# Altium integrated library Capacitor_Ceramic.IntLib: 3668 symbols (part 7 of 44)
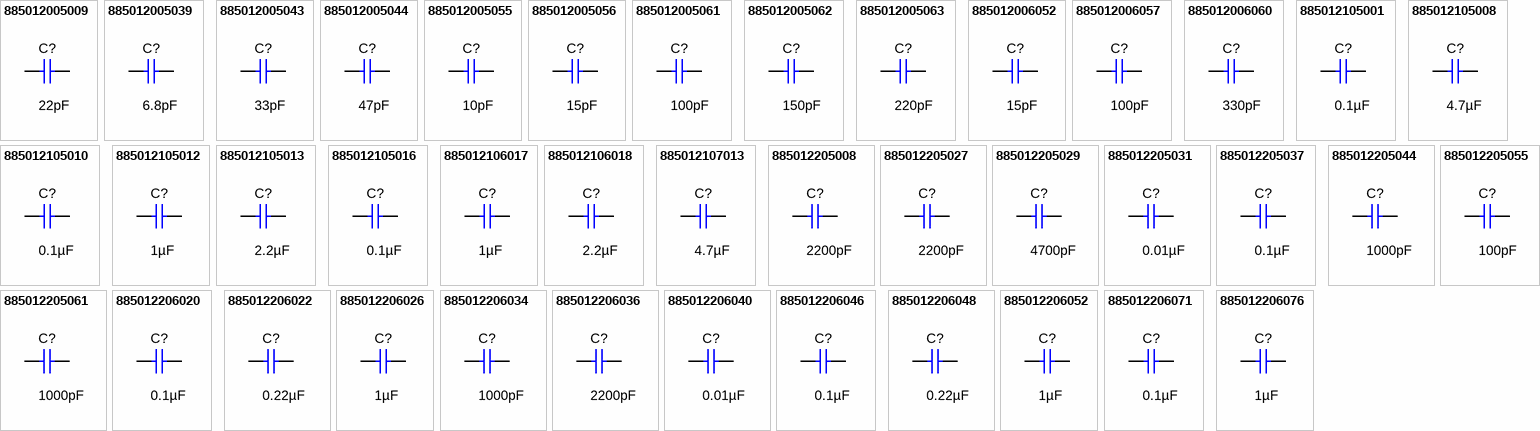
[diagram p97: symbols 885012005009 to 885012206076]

## 885012206076
designator C?  ValueDisplayed: 1µF  (hidden comment: 885012206076)
CAP, CERM, 1 µF, 25 V,+/- 10%, X7R, 0603; Manufacturer: Wurth Elektronik; Polarized: N; CompType: Capacitor; Value: 1uF; U/M: EA; Cap_F: 0.000001; Tolerance_%: 10; VDC_V: 25; Value2: 25V; TaMin_C: -55; TaMax_C: 125; Cap_Case: 0603; SizeArea_mm2: 1.28; SizeAreaWB_mm2: 4.68; SizeX_mm: 1.6; SizeY_mm: 0.8; SizeZ_mm: 1; AEC Category: Q200; Green_Lifecycle: Not Set; Green_REACh: Incomplete
signal-integrity model Cap
simulation model Cap
footprint 0603
footprint 0603M
footprint 0603L
footprint 0603_HV
footprint 0603S
pins: 1, 2

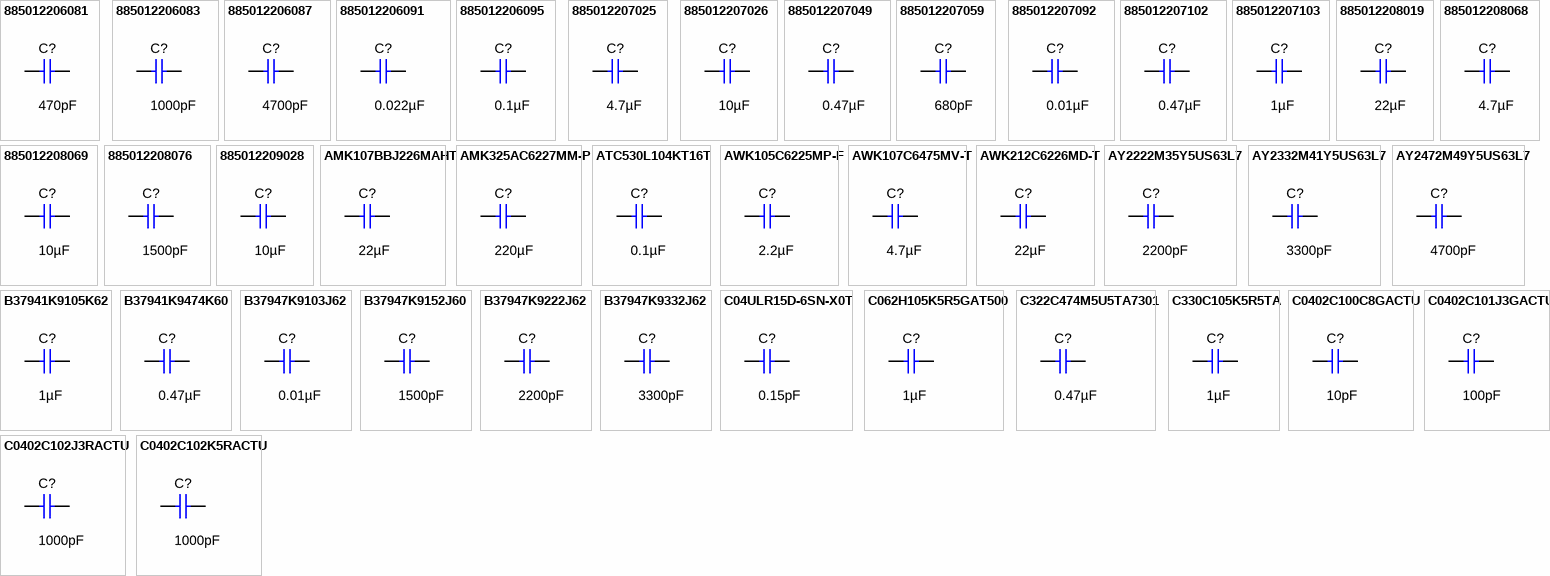
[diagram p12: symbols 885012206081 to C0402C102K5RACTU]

## 885012206081
designator C?  ValueDisplayed: 470pF  (hidden comment: 885012206081)
CAP, CERM, 470 pF, 50 V,+/- 10%, X7R, 0603; Manufacturer: Wurth Elektronik; Polarized: N; CompType: Capacitor; Value: 470pF; U/M: EA; Cap_F: 0.00000000047; Tolerance_%: 10; VDC_V: 50; Value2: 50V; TaMin_C: -55; TaMax_C: 125; Cap_Case: 0603; SizeArea_mm2: 1.28; SizeAreaWB_mm2: 4.68; SizeX_mm: 1.6; SizeY_mm: 0.8; SizeZ_mm: 1; AEC Category: Q200; Green_Lifecycle: Active; Green_REACh: Passed
signal-integrity model Cap
simulation model Cap
footprint 0603
footprint 0603M
footprint 0603L
footprint 0603_HV
footprint 0603S
pins: 1, 2

## 885012206083
designator C?  ValueDisplayed: 1000pF  (hidden comment: 885012206083)
CAP, CERM, 1000 pF, 50 V,+/- 10%, X7R, 0603; Manufacturer: Wurth Elektronik; Polarized: N; CompType: Capacitor; Value: 1000pF; U/M: EA; Cap_F: 0.000000001; Tolerance_%: 10; VDC_V: 50; Value2: 50V; TaMin_C: -55; TaMax_C: 125; Cap_Case: 0603; SizeArea_mm2: 1.28; SizeAreaWB_mm2: 4.68; SizeX_mm: 1.6; SizeY_mm: 0.8; SizeZ_mm: 1; AEC Category: Q200
signal-integrity model Cap
simulation model Cap
footprint 0603
footprint 0603M
footprint 0603L
footprint 0603_HV
footprint 0603S
pins: 1, 2

## 885012206087
designator C?  ValueDisplayed: 4700pF  (hidden comment: 885012206087)
CAP, CERM, 4700 pF, 50 V,+/- 10%, X7R, 0603; Manufacturer: Wurth Elektronik; Polarized: N; CompType: Capacitor; Value: 4700pF; U/M: EA; Cap_F: 0.0000000047; Tolerance_%: 10; VDC_V: 50; Value2: 50V; TaMin_C: -55; TaMax_C: 125; Cap_Case: 0603; SizeArea_mm2: 1.28; SizeAreaWB_mm2: 4.68; SizeX_mm: 1.6; SizeY_mm: 0.8; SizeZ_mm: 1; AEC Category: Q200
signal-integrity model Cap
simulation model Cap
footprint 0603
footprint 0603M
footprint 0603L
footprint 0603_HV
footprint 0603S
pins: 1, 2

## 885012206091
designator C?  ValueDisplayed: 0.022µF  (hidden comment: 885012206091)
CAP, CERM, 0.022 µF, 50 V,+/- 10%, X7R, 0603; Manufacturer: Wurth Elektronik; Polarized: N; CompType: Capacitor; Value: 0.022uF; U/M: EA; Cap_F: 0.000000022; Tolerance_%: 10; VDC_V: 50; Value2: 50V; TaMin_C: -55; TaMax_C: 125; Cap_Case: 0603; SizeArea_mm2: 1.28; SizeAreaWB_mm2: 4.68; SizeX_mm: 1.6; SizeY_mm: 0.8; SizeZ_mm: 1; AEC Category: Q200; Green_Lifecycle: Active; Green_REACh: Passed
signal-integrity model Cap
simulation model Cap
footprint 0603
footprint 0603M
footprint 0603L
footprint 0603_HV
footprint 0603S
pins: 1, 2

## 885012206095
designator C?  ValueDisplayed: 0.1µF  (hidden comment: 885012206095)
CAP, CERM, 0.1 µF, 50 V,+/- 10%, X7R, 0603; Manufacturer: Wurth Elektronik; Polarized: N; CompType: Capacitor; Value: 0.1uF; U/M: EA; Cap_F: 0.0000001; Tolerance_%: 10; VDC_V: 50; Value2: 50V; TaMin_C: -55; TaMax_C: 125; Cap_Case: 0603; SizeArea_mm2: 1.28; SizeAreaWB_mm2: 4.68; SizeX_mm: 1.6; SizeY_mm: 0.8; SizeZ_mm: 1; AEC Category: Q200; Green_Lifecycle: Active; Green_REACh: Passed
signal-integrity model Cap
simulation model Cap
footprint 0603
footprint 0603M
footprint 0603L
footprint 0603_HV
footprint 0603S
pins: 1, 2

## 885012207025
designator C?  ValueDisplayed: 4.7µF  (hidden comment: 885012207025)
CAP, CERM, 4.7 µF, 10 V,+/- 10%, X7R, 0805; Manufacturer: Wurth Elektronik; Polarized: N; CompType: Capacitor; Value: 4.7uF; U/M: EA; Cap_F: 0.0000047; Tolerance_%: 10; Value2: 10V; TaMin_C: -55; TaMax_C: 125; Cap_Case: 0805; SizeArea_mm2: 2.5; SizeAreaWB_mm2: 6.75; SizeX_mm: 2; SizeY_mm: 1.25; SizeZ_mm: 1.45; AEC Category: Q200
signal-integrity model Cap
simulation model Cap
footprint 0805_HV
footprint 0805_HV1
footprint 0805
footprint 0805M
footprint 0805L
pins: 1, 2

## 885012207026
designator C?  ValueDisplayed: 10µF  (hidden comment: 885012207026)
CAP, CERM, 10 µF, 10 V,+/- 10%, X7R, 0805; Manufacturer: Wurth Elektronik; Polarized: N; CompType: Capacitor; Value: 10uF; U/M: EA; Cap_F: 0.00001; Tolerance_%: 10; Value2: 10V; TaMin_C: -55; TaMax_C: 125; Cap_Case: 0805; SizeArea_mm2: 2.5; SizeAreaWB_mm2: 6.75; SizeX_mm: 2; SizeY_mm: 1.25; SizeZ_mm: 1.45; AEC Category: Q200
signal-integrity model Cap
simulation model Cap
footprint 0805_HV
footprint 0805_HV1
footprint 0805
footprint 0805M
footprint 0805L
pins: 1, 2

## 885012207049
designator C?  ValueDisplayed: 0.47µF  (hidden comment: 885012207049)
CAP, CERM, 0.47 µF, 16 V,+/- 10%, X7R, 0805; Manufacturer: Wurth Elektronik; Polarized: N; CompType: Capacitor; Value: 0.47uF; U/M: EA; Cap_F: 0.00000047; Tolerance_%: 10; VDC_V: 16; Value2: 16V; TaMin_C: -55; TaMax_C: 125; Cap_Case: 0805; SizeArea_mm2: 2.5; SizeAreaWB_mm2: 6.75; SizeX_mm: 2; SizeY_mm: 1.25; SizeZ_mm: 1.45; AEC Category: Q200
signal-integrity model Cap
simulation model Cap
footprint 0805_HV
footprint 0805_HV1
footprint 0805
footprint 0805M
footprint 0805L
pins: 1, 2

## 885012207059
designator C?  ValueDisplayed: 680pF  (hidden comment: 885012207059)
CAP, CERM, 680 pF, 25 V,+/- 10%, X7R, 0805; Manufacturer: Wurth Elektronik; Polarized: N; CompType: Capacitor; Value: 680pF; U/M: EA; Cap_F: 0.00000000068; Tolerance_%: 10; VDC_V: 25; Value2: 25V; TaMin_C: -55; TaMax_C: 125; Cap_Case: 0805; SizeArea_mm2: 2.5; SizeAreaWB_mm2: 6.75; SizeX_mm: 2; SizeY_mm: 1.25; SizeZ_mm: 1.45; AEC Category: Q200; Green_Lifecycle: Not Set; Green_REACh: Incomplete
signal-integrity model Cap
simulation model Cap
footprint 0805_HV
footprint 0805_HV1
footprint 0805
footprint 0805M
footprint 0805L
pins: 1, 2

## 885012207092
designator C?  ValueDisplayed: 0.01µF  (hidden comment: 885012207092)
CAP, CERM, 0.01 µF, 50 V,+/- 10%, X7R, 0805; Manufacturer: Wurth Elektronik; Polarized: N; CompType: Capacitor; Value: 0.01uF; U/M: EA; Cap_F: 0.00000001; Tolerance_%: 10; VDC_V: 50; Value2: 50V; TaMin_C: -55; TaMax_C: 125; Cap_Case: 0805; SizeArea_mm2: 2.5; SizeAreaWB_mm2: 6.75; SizeX_mm: 2; SizeY_mm: 1.25; SizeZ_mm: 1.45; AEC Category: Q200; Green_Lifecycle: Not Set; Green_REACh: Incomplete
signal-integrity model Cap
simulation model Cap
footprint 0805_HV
footprint 0805_HV1
footprint 0805
footprint 0805M
footprint 0805L
pins: 1, 2

## 885012207102
designator C?  ValueDisplayed: 0.47µF  (hidden comment: 885012207102)
CAP, CERM, 0.47 µF, 50 V,+/- 10%, X7R, 0805; Manufacturer: Wurth Elektronik; Polarized: N; CompType: Capacitor; Value: 0.47uF; U/M: EA; Cap_F: 0.00000047; Tolerance_%: 10; VDC_V: 50; Value2: 50V; TaMin_C: -55; TaMax_C: 125; Cap_Case: 0805; SizeArea_mm2: 2.5; SizeAreaWB_mm2: 6.75; SizeX_mm: 2; SizeY_mm: 1.25; SizeZ_mm: 1.45; AEC Category: Q200
signal-integrity model Cap
simulation model Cap
footprint 0805_HV
footprint 0805_HV1
footprint 0805
footprint 0805M
footprint 0805L
pins: 1, 2

## 885012207103
designator C?  ValueDisplayed: 1µF  (hidden comment: 885012207103)
CAP, CERM, 1 µF, 50 V,+/- 10%, X7R, 0805; Manufacturer: Wurth Elektronik; Polarized: N; CompType: Capacitor; Value: 1uF; U/M: EA; Cap_F: 0.000001; Tolerance_%: 10; VDC_V: 50; Value2: 50V; TaMin_C: -55; TaMax_C: 125; Cap_Case: 0805; SizeArea_mm2: 2.5; SizeAreaWB_mm2: 6.75; SizeX_mm: 2; SizeY_mm: 1.25; SizeZ_mm: 1.45; AEC Category: Q200
signal-integrity model Cap
simulation model Cap
footprint 0805_HV
footprint 0805_HV1
footprint 0805
footprint 0805M
footprint 0805L
pins: 1, 2

## 885012208019
designator C?  ValueDisplayed: 22µF  (hidden comment: 885012208019)
CAP, CERM, 22 µF, 10 V,+/- 10%, X7R, 1206; Manufacturer: Wurth Elektronik; Polarized: N; CompType: Capacitor; Value: 22uF; U/M: EA; Cap_F: 0.000022; Tolerance_%: 10; Value2: 10V; TaMin_C: -55; TaMax_C: 125; Cap_Case: 1206; SizeArea_mm2: 5.12; SizeAreaWB_mm2: 10.92; SizeX_mm: 3.2; SizeY_mm: 1.6; SizeZ_mm: 1.9; AEC Category: Q200
signal-integrity model Cap
simulation model Cap
footprint 1206_190
footprint 1206_190M
footprint 1206_190L
pins: 1, 2

## 885012208068
designator C?  ValueDisplayed: 4.7µF  (hidden comment: 885012208068)
CAP, CERM, 4.7 µF, 25 V,+/- 10%, X7R, 1206; Manufacturer: Wurth Elektronik; Polarized: N; CompType: Capacitor; Value: 4.7uF; U/M: EA; Cap_F: 0.0000047; Tolerance_%: 10; VDC_V: 25; Value2: 25V; TaMin_C: -55; TaMax_C: 125; Cap_Case: 1206; SizeArea_mm2: 5.12; SizeAreaWB_mm2: 10.92; SizeX_mm: 3.2; SizeY_mm: 1.6; SizeZ_mm: 1.9; AEC Category: Q200; Green_Lifecycle: Active; Green_REACh: Passed
signal-integrity model Cap
simulation model Cap
footprint 1206_190
footprint 1206_190M
footprint 1206_190L
pins: 1, 2

## 885012208069
designator C?  ValueDisplayed: 10µF  (hidden comment: 885012208069)
CAP, CERM, 10 µF, 25 V,+/- 10%, X7R, 1206; Manufacturer: Wurth Elektronik; Polarized: N; CompType: Capacitor; Value: 10uF; U/M: EA; Cap_F: 0.00001; Tolerance_%: 10; VDC_V: 25; Value2: 25V; TaMin_C: -55; TaMax_C: 125; Cap_Case: 1206; SizeArea_mm2: 5.12; SizeAreaWB_mm2: 10.92; SizeX_mm: 3.2; SizeY_mm: 1.6; SizeZ_mm: 1.35; AEC Category: Q200; Green_Lifecycle: Not Set; Green_REACh: Incomplete
signal-integrity model Cap
simulation model Cap
footprint 1206
footprint 1206M
footprint 1206L
pins: 1, 2

## 885012208076
designator C?  ValueDisplayed: 1500pF  (hidden comment: 885012208076)
CAP, CERM, 1500 pF, 50 V,+/- 10%, X7R, 1206; Manufacturer: Wurth Elektronik; Polarized: N; CompType: Capacitor; Value: 1500pF; U/M: EA; Cap_F: 0.0000000015; Tolerance_%: 10; VDC_V: 50; Value2: 50V; TaMin_C: -55; TaMax_C: 125; Cap_Case: 1206; SizeArea_mm2: 5.12; SizeAreaWB_mm2: 10.92; SizeX_mm: 3.2; SizeY_mm: 1.6; SizeZ_mm: 1.35; AEC Category: Q200
signal-integrity model Cap
simulation model Cap
footprint 1206
footprint 1206M
footprint 1206L
pins: 1, 2

## 885012209028
designator C?  ValueDisplayed: 10µF  (hidden comment: 885012209028)
CAP, CERM, 10 µF, 25 V,+/- 10%, X7R, 1210; Manufacturer: Wurth Elektronik; Polarized: N; CompType: Capacitor; Value: 10uF; U/M: EA; Cap_F: 0.00001; Tolerance_%: 10; VDC_V: 25; Value2: 25V; TaMin_C: -55; TaMax_C: 125; Cap_Case: 1210; SizeArea_mm2: 8; SizeAreaWB_mm2: 14.7; SizeX_mm: 3.2; SizeY_mm: 2.5; SizeZ_mm: 2.2; AEC Category: Q200
signal-integrity model Cap
simulation model Cap
footprint 1210_220
footprint 1210_220M
footprint 1210_220L
pins: 1, 2

## AMK107BBJ226MAHT
designator C?  ValueDisplayed: 22µF  (hidden comment: AMK107BBJ226MAHT)
CAP, CERM, 22 µF, 4 V,+/- 20%, X5R, AEC-Q200 Grade 3, 0603; Manufacturer: Taiyo Yuden; Polarized: N; CompType: Capacitor; Value: 22uF; U/M: EA; Cap_F: 0.000022; Tolerance_%: 20; VDC_V: 4; Value2: 4V; TaMin_C: -55; TaMax_C: 85; Cap_Case: 0603; SizeArea_mm2: 1.28; SizeAreaWB_mm2: 4.68; SizeX_mm: 1.6; SizeY_mm: 0.8; SizeZ_mm: 1; AEC Category: Q200; AEC Qualified: Y; AEC Grade: 3
signal-integrity model Cap
simulation model Cap
footprint 0603
footprint 0603M
footprint 0603L
footprint 0603_HV
footprint 0603S
pins: 1, 2

## AMK325AC6227MM-P
designator C?  ValueDisplayed: 220µF  (hidden comment: AMK325AC6227MM-P)
CAP, CERM, 220 µF, 4 V,+/- 10%, X6S, 1210; Manufacturer: Taiyo Yuden; Polarized: N; CompType: Capacitor; Value: 220uF; U/M: EA; Cap_F: 0.00022; Tolerance_%: 10; VDC_V: 4; Value2: 4V; TaMin_C: -55; TaMax_C: 105; Cap_Case: 1210; SizeArea_mm2: 8; SizeAreaWB_mm2: 14.7; SizeX_mm: 3.2; SizeY_mm: 2.5; SizeZ_mm: 2.8; AEC Category: Q200; Green_Lifecycle: Not Set; Green_REACh: Incomplete
signal-integrity model Cap
simulation model Cap
footprint 1210_280
pins: 1, 2

## ATC530L104KT16T
designator C?  ValueDisplayed: 0.1µF  (hidden comment: ATC530L104KT16T)
CAP, CERM, 0.1 µF, 16 V,+/- 10%, X7R, 0402; Manufacturer: AT Ceramics; Polarized: N; CompType: Capacitor; Value: 0.1uF; U/M: EA; Cap_F: 0.0000001; Tolerance_%: 10; VDC_V: 16; Value2: 16V; TaMin_C: -55; TaMax_C: 125; Cap_Case: 0402; SizeArea_mm2: 0.5; SizeAreaWB_mm2: 3; SizeX_mm: 1; SizeZ_mm: 0.6; AEC Category: Q200
signal-integrity model Cap
simulation model Cap
footprint 0402
footprint 0402M
footprint 0402L
footprint 0402S
pins: 1, 2

## AWK105C6225MP-F
designator C?  ValueDisplayed: 2.2µF  (hidden comment: AWK105C6225MP-F)
CAP, CERM, 2.2 µF, 4 V,+/- 20%, X6S, SMD, Body 1x0.52mm; Manufacturer: Taiyo Yuden; Polarized: N; CompType: Capacitor; Value: 2.2uF; U/M: EA; Cap_F: 0.0000022; Tolerance_%: 20; VDC_V: 4; Value2: 4V; TaMin_C: -55; TaMax_C: 105; Cap_Case: 0204; SizeArea_mm2: 0.5; SizeAreaWB_mm2: 3; SizeY_mm: 1; SizeZ_mm: 0.35; AEC Category: Q200
signal-integrity model Cap
simulation model Cap
footprint 0204
pins: 1, 2

## AWK107C6475MV-T
designator C?  ValueDisplayed: 4.7µF  (hidden comment: AWK107C6475MV-T)
CAP, CERM, 4.7 µF, 4 V,+/- 20%, X6S, 0306; Manufacturer: Taiyo Yuden; Polarized: N; CompType: Capacitor; Value: 4.7uF; U/M: EA; Cap_F: 0.0000047; Tolerance_%: 20; VDC_V: 4; Value2: 4V; TaMin_C: -55; TaMax_C: 105; Cap_Case: 0306; SizeArea_mm2: 1.28; SizeAreaWB_mm2: 4.68; SizeX_mm: 0.8; SizeY_mm: 1.6; SizeZ_mm: 0.6; AEC Category: Q200
signal-integrity model Cap
simulation model Cap
footprint 0306
pins: 1, 2

## AWK212C6226MD-T
designator C?  ValueDisplayed: 22µF  (hidden comment: AWK212C6226MD-T)
CAP, CERM, 22 µF, 4 V,+/- 20%, X6S, 0508; Manufacturer: Taiyo Yuden; Polarized: N; CompType: Capacitor; Value: 22uF; U/M: EA; Cap_F: 0.000022; Tolerance_%: 20; VDC_V: 4; Value2: 4V; TaMin_C: -55; TaMax_C: 105; Cap_Case: 0508; SizeArea_mm2: 2.5; SizeAreaWB_mm2: 6.75; SizeX_mm: 1.25; SizeY_mm: 2; SizeZ_mm: 1; AEC Category: Q200
signal-integrity model Cap
simulation model Cap
footprint 0508
pins: 1, 2

## AY2222M35Y5US63L7
designator C?  ValueDisplayed: 2200pF  (hidden comment: AY2222M35Y5US63L7)
CAP, CERM, 2200 pF, X1 440 VAC/Y2 300 VAC, +/- 20%, Y5U, AEC-Q200 Grade 1, D9.5xT5mm; Manufacturer: Vishay-Bccomponents; Polarized: N; CompType: Capacitor; Value: 2200pF; U/M: EA; Cap_F: 0.0000000022; Tolerance_%: 20; TaMin_C: -55; TaMax_C: 125; Cap_Case: 9.5x5mm; SizeArea_mm2: 47.5; SizeAreaWB_mm2: 80.5; SizeX_mm: 9.5; SizeY_mm: 5; SizeZ_mm: 14.5; AEC Category: Q200; AEC Qualified: Y; AEC Grade: 1; AC_Safety: X1Y2; VAC_X: 440; VAC_Y: 300
signal-integrity model Cap
simulation model Cap
footprint AY2_950x500_Straight
pins: 1, 2

## AY2332M41Y5US63L7
designator C?  ValueDisplayed: 3300pF  (hidden comment: AY2332M41Y5US63L7)
CAP, CERM, 3300 pF, X1 440 VAC/Y2 300 VAC, +/- 20%, Y5U, AEC-Q200 Grade 1, D11xT5mm; Manufacturer: Vishay-Bccomponents; Polarized: N; CompType: Capacitor; Value: 3300pF; U/M: EA; Cap_F: 0.0000000033; Tolerance_%: 20; TaMin_C: -55; TaMax_C: 125; Cap_Case: 11x5mm; SizeArea_mm2: 55; SizeAreaWB_mm2: 91; SizeX_mm: 11; SizeY_mm: 5; SizeZ_mm: 16; AEC Category: Q200; AEC Qualified: Y; AEC Grade: 1; AC_Safety: X1Y2; VAC_X: 440; VAC_Y: 300
signal-integrity model Cap
simulation model Cap
footprint AY2_1100x500_Straight
pins: 1, 2

## AY2472M49Y5US63L7
designator C?  ValueDisplayed: 4700pF  (hidden comment: AY2472M49Y5US63L7)
CAP, CERM, 4700 pF, X1 440 VAC/Y2 300 VAC, +/- 20%, Y5U, AEC-Q200 Grade 1, D13xT5mm; Manufacturer: Vishay-Bccomponents; Polarized: N; CompType: Capacitor; Value: 4700pF; U/M: EA; Cap_F: 0.0000000047; Tolerance_%: 20; TaMin_C: -55; TaMax_C: 125; Cap_Case: 13x5mm; SizeArea_mm2: 65; SizeAreaWB_mm2: 105; SizeX_mm: 13; SizeY_mm: 5; SizeZ_mm: 18; AEC Category: Q200; AEC Qualified: Y; AEC Grade: 1; AC_Safety: X1Y2; VAC_X: 440; VAC_Y: 300
signal-integrity model Cap
simulation model Cap
footprint AY2_1300x500_Straight
pins: 1, 2

## B37941K9105K62
designator C?  ValueDisplayed: 1µF  (hidden comment: B37941K9105K62)
CAP, CERM, 1 µF, 16 V,+/- 10%, X7R, 0805; Manufacturer: TDK; Polarized: N; CompType: Capacitor; Value: 1uF; U/M: EA; Cap_F: 0.000001; Tolerance_%: 10; VDC_V: 16; Value2: 16V; TaMin_C: -55; TaMax_C: 125; Cap_Case: 0805; SizeArea_mm2: 2.5; SizeAreaWB_mm2: 6.75; SizeX_mm: 2; SizeY_mm: 1.25; SizeZ_mm: 1.45; AEC Category: Q200
signal-integrity model Cap
simulation model Cap
footprint 0805_HV
footprint 0805_HV1
footprint 0805
footprint 0805M
footprint 0805L
pins: 1, 2

## B37941K9474K60
designator C?  ValueDisplayed: 0.47µF  (hidden comment: B37941K9474K60)
CAP, CERM, 0.47 µF, 16 V,+/- 10%, X7R, 0805; Manufacturer: TDK; Polarized: N; CompType: Capacitor; Value: 0.47uF; U/M: EA; Cap_F: 0.00000047; Tolerance_%: 10; VDC_V: 16; Value2: 16V; TaMin_C: -55; TaMax_C: 125; Cap_Case: 0805; SizeArea_mm2: 2.5; SizeAreaWB_mm2: 6.75; SizeX_mm: 2; SizeY_mm: 1.25; SizeZ_mm: 1.45; AEC Category: Q200
signal-integrity model Cap
simulation model Cap
footprint 0805_HV
footprint 0805_HV1
footprint 0805
footprint 0805M
footprint 0805L
pins: 1, 2

## B37947K9103J62
designator C?  ValueDisplayed: 0.01µF  (hidden comment: B37947K9103J62)
CAP, CERM, 0.01 µF, 16 V,+/- 5%, C0G/NP0, 0805; Manufacturer: TDK; Polarized: N; CompType: Capacitor; Value: 0.01uF; U/M: EA; Cap_F: 0.00000001; Tolerance_%: 5; VDC_V: 16; Value2: 16V; TaMin_C: -55; TaMax_C: 125; Cap_Case: 0805; SizeArea_mm2: 2.5; SizeAreaWB_mm2: 6.75; SizeX_mm: 2; SizeY_mm: 1.25; SizeZ_mm: 1.45; AEC Category: Q200
signal-integrity model Cap
simulation model Cap
footprint 0805_HV
footprint 0805_HV1
footprint 0805
footprint 0805M
footprint 0805L
pins: 1, 2

## B37947K9152J60
designator C?  ValueDisplayed: 1500pF  (hidden comment: B37947K9152J60)
CAP, CERM, 1500 pF, 16 V,+/- 5%, C0G/NP0, 0805; Manufacturer: TDK; Polarized: N; CompType: Capacitor; Value: 1500pF; U/M: EA; Cap_F: 0.0000000015; Tolerance_%: 5; VDC_V: 16; Value2: 16V; TaMin_C: -55; TaMax_C: 125; Cap_Case: 0805; SizeArea_mm2: 2.5; SizeAreaWB_mm2: 6.75; SizeX_mm: 2; SizeY_mm: 1.25; SizeZ_mm: 1.45; AEC Category: Q200
signal-integrity model Cap
simulation model Cap
footprint 0805_HV
footprint 0805_HV1
footprint 0805
footprint 0805M
footprint 0805L
pins: 1, 2

## B37947K9222J62
designator C?  ValueDisplayed: 2200pF  (hidden comment: B37947K9222J62)
CAP, CERM, 2200 pF, 16 V,+/- 5%, C0G/NP0, 0805; Manufacturer: TDK; Polarized: N; CompType: Capacitor; Value: 2200pF; U/M: EA; Cap_F: 0.0000000022; Tolerance_%: 5; VDC_V: 16; Value2: 16V; TaMin_C: -55; TaMax_C: 125; Cap_Case: 0805; SizeArea_mm2: 2.5; SizeAreaWB_mm2: 6.75; SizeX_mm: 2; SizeY_mm: 1.25; SizeZ_mm: 1.45; AEC Category: Q200
signal-integrity model Cap
simulation model Cap
footprint 0805_HV
footprint 0805_HV1
footprint 0805
footprint 0805M
footprint 0805L
pins: 1, 2

## B37947K9332J62
designator C?  ValueDisplayed: 3300pF  (hidden comment: B37947K9332J62)
CAP, CERM, 3300 pF, 16 V,+/- 5%, C0G/NP0, 0805; Manufacturer: TDK; Polarized: N; CompType: Capacitor; Value: 3300pF; U/M: EA; Cap_F: 0.0000000033; Tolerance_%: 5; VDC_V: 16; Value2: 16V; TaMin_C: -55; TaMax_C: 125; Cap_Case: 0805; SizeArea_mm2: 2.5; SizeAreaWB_mm2: 6.75; SizeX_mm: 2; SizeY_mm: 1.25; SizeZ_mm: 1.45; AEC Category: Q200
signal-integrity model Cap
simulation model Cap
footprint 0805_HV
footprint 0805_HV1
footprint 0805
footprint 0805M
footprint 0805L
pins: 1, 2

## C04ULR15D-6SN-X0T
designator C?  ValueDisplayed: 0.15pF  (hidden comment: C04ULR15D-6SN-X0T)
CAP, CERM, 0.15 pF, 200 V,+/- %, X7R, 0402; Manufacturer: Knowles Capacitors; Polarized: N; CompType: Capacitor; Value: 0.15pF; U/M: EA; Cap_F: 0.00000000000015; VDC_V: 200; Value2: 200V; TaMin_C: -55; TaMax_C: 125; Cap_Case: 0402; SizeArea_mm2: 0.5; SizeAreaWB_mm2: 3; SizeX_mm: 1; SizeZ_mm: 0.7; AEC Category: Q200
signal-integrity model Cap
simulation model Cap
footprint 0402_070
pins: 1, 2

## C062H105K5R5GAT500
designator C?  ValueDisplayed: 1µF  (hidden comment: C062H105K5R5GAT500)
CAP, CERM, 1 µF, 50 V,+/- 10%, X7R, 7.37x7.37x2.29mm; Manufacturer: Kemet; Polarized: N; CompType: Capacitor; Value: 1uF; U/M: EA; Cap_F: 0.000001; Tolerance_%: 10; VDC_V: 50; Value2: 50V; TaMin_C: -55; TaMax_C: 200; SizeArea_mm2: 16.8773; SizeAreaWB_mm2: 40.1973; SizeX_mm: 7.37; SizeY_mm: 2.29; AEC Category: Q200
signal-integrity model Cap
simulation model Cap
footprint KEMET_737x737x229
pins: 1, 2

## C322C474M5U5TA7301
designator C?  ValueDisplayed: 0.47µF  (hidden comment: C322C474M5U5TA7301)
CAP, CERM, 0.47 µF, 50 V,+/- 20%, Z5U, 5.08x3.18mm; Manufacturer: Kemet; Polarized: N; CompType: Capacitor; Value: 0.47uF; U/M: EA; Cap_F: 0.00000047; Tolerance_%: 20; VDC_V: 50; Value2: 50V; TaMin_C: -10; TaMax_C: 85; Cap_Case: 5.08x3.18x6.6mm; SizeArea_mm2: 16.1544; SizeAreaWB_mm2: 36.6744; SizeX_mm: 5.08; SizeY_mm: 3.18; SizeZ_mm: 6.6; AEC Category: Q200
signal-integrity model Cap
simulation model Cap
footprint C322_508x318x660
pins: 1, 2

## C330C105K5R5TA
designator C?  ValueDisplayed: 1µF  (hidden comment: C330C105K5R5TA)
CAP, CERM, 1 µF, 50 V,+/- 10%, X7R, 7.11x4.07mm; Manufacturer: Kemet; Polarized: N; CompType: Capacitor; Value: 1uF; U/M: EA; Cap_F: 0.000001; Tolerance_%: 10; VDC_V: 50; Value2: 50V; TaMin_C: -55; TaMax_C: 125; Cap_Case: 7.11x4.07x9.14mm; SizeArea_mm2: 28.9377; SizeAreaWB_mm2: 55.2977; SizeX_mm: 7.11; SizeY_mm: 4.07; SizeZ_mm: 9.14; AEC Category: Q200
signal-integrity model Cap
simulation model Cap
footprint C330_711x407x914
pins: 1, 2

## C0402C100C8GACTU
designator C?  ValueDisplayed: 10pF  (hidden comment: C0402C100C8GACTU)
CAP, CERM, 10 pF, 10 V,+/- 2.5%, C0G/NP0, 0402; Manufacturer: Kemet; Polarized: N; CompType: Capacitor; Value: 10pF; U/M: EA; Cap_F: 0.00000000001; Tolerance_%: 2.5; VDC_V: 10; Value2: 10V; TaMin_C: -55; TaMax_C: 125; Cap_Case: 0402; SizeArea_mm2: 0.5; SizeAreaWB_mm2: 3; SizeX_mm: 1; SizeZ_mm: 0.6; AEC Category: Q200
signal-integrity model Cap
simulation model Cap
footprint 0402
footprint 0402M
footprint 0402L
footprint 0402S
pins: 1, 2

## C0402C101J3GACTU
designator C?  ValueDisplayed: 100pF  (hidden comment: C0402C101J3GACTU)
CAP, CERM, 100 pF, 25 V,+/- 5%, C0G/NP0, 0402; Manufacturer: Kemet; Polarized: N; CompType: Capacitor; Value: 100pF; U/M: EA; Cap_F: 0.0000000001; Tolerance_%: 5; VDC_V: 25; Value2: 25V; TaMin_C: -55; TaMax_C: 125; Cap_Case: 0402; SizeArea_mm2: 0.5; SizeAreaWB_mm2: 3; SizeX_mm: 1; SizeZ_mm: 0.6; AEC Category: Q200; Green_Lifecycle: Active; Green_REACh: Passed
signal-integrity model Cap
simulation model Cap
footprint 0402
footprint 0402M
footprint 0402L
footprint 0402S
pins: 1, 2

## C0402C102J3RACTU
designator C?  ValueDisplayed: 1000pF  (hidden comment: C0402C102J3RACTU)
CAP, CERM, 1000 pF, 25 V,+/- 5%, X7R, 0402; Manufacturer: Kemet; Polarized: N; CompType: Capacitor; Value: 1000pF; U/M: EA; Cap_F: 0.000000001; Tolerance_%: 5; VDC_V: 25; Value2: 25V; TaMin_C: -55; TaMax_C: 125; Cap_Case: 0402; SizeArea_mm2: 0.5; SizeAreaWB_mm2: 3; SizeX_mm: 1; SizeZ_mm: 0.6; AEC Category: Q200; Green_Lifecycle: Active; Green_REACh: Passed
signal-integrity model Cap
simulation model Cap
footprint 0402
footprint 0402M
footprint 0402L
footprint 0402S
pins: 1, 2

## C0402C102K5RACTU
designator C?  ValueDisplayed: 1000pF  (hidden comment: C0402C102K5RACTU)
CAP, CERM, 1000 pF, 50 V,+/- 10%, X7R, 0402; Manufacturer: Kemet; Polarized: N; CompType: Capacitor; Value: 1000pF; U/M: EA; Cap_F: 0.000000001; Tolerance_%: 10; VDC_V: 50; Value2: 50V; TaMin_C: -55; TaMax_C: 125; Cap_Case: 0402; SizeArea_mm2: 0.5; SizeAreaWB_mm2: 3; SizeX_mm: 1; SizeZ_mm: 0.6; AEC Category: Q200; Green_Lifecycle: Active; Green_REACh: Passed
signal-integrity model Cap
simulation model Cap
footprint 0402
footprint 0402M
footprint 0402L
footprint 0402S
pins: 1, 2

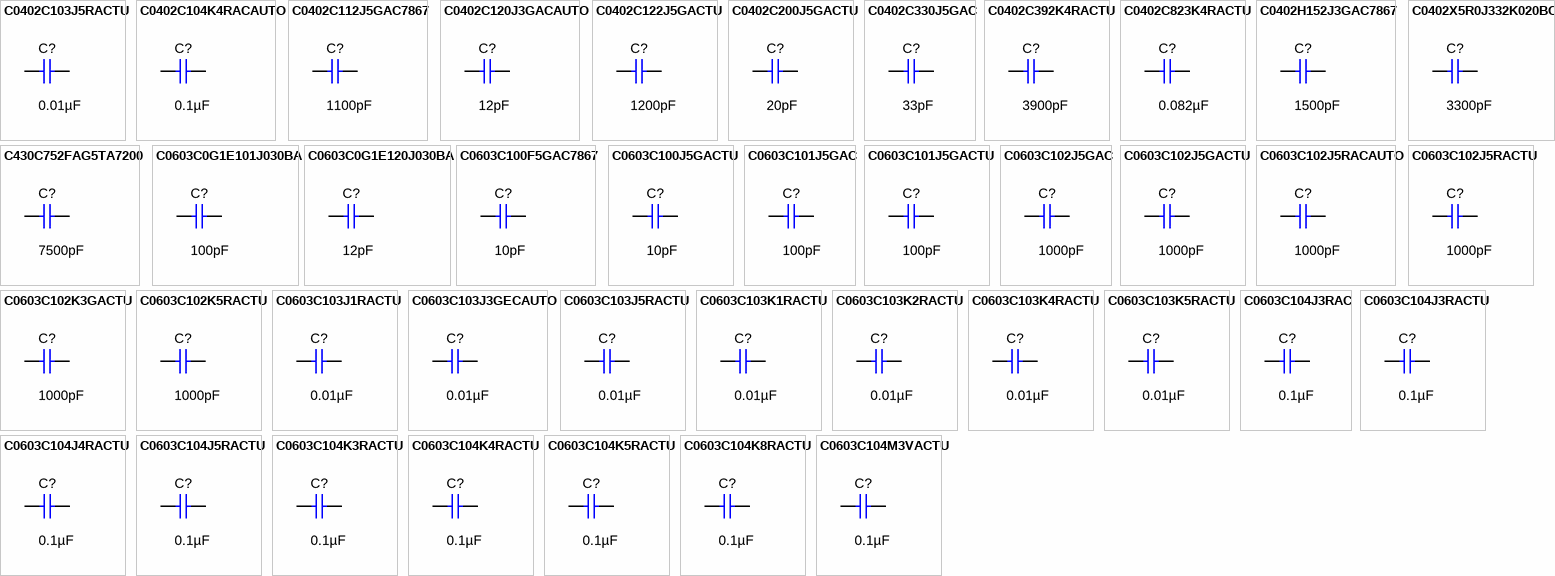
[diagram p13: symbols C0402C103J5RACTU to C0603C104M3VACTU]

## C0402C103J5RACTU
designator C?  ValueDisplayed: 0.01µF  (hidden comment: C0402C103J5RACTU)
CAP, CERM, 0.01 µF, 50 V,+/- 5%, X7R, 0402; Manufacturer: Kemet; Polarized: N; CompType: Capacitor; Value: 0.01uF; U/M: EA; Cap_F: 0.00000001; Tolerance_%: 5; VDC_V: 50; Value2: 50V; TaMin_C: -55; TaMax_C: 125; Cap_Case: 0402; SizeArea_mm2: 0.5; SizeAreaWB_mm2: 3; SizeX_mm: 1; SizeZ_mm: 0.6; AEC Category: Q200; Green_Lifecycle: Active; Green_REACh: Passed
signal-integrity model Cap
simulation model Cap
footprint 0402
footprint 0402M
footprint 0402L
footprint 0402S
pins: 1, 2

## C0402C104K4RACAUTO
designator C?  ValueDisplayed: 0.1µF  (hidden comment: C0402C104K4RACAUTO)
CAP, CERM, 0.1 µF, 16 V,+/- 10%, X7R, AEC-Q200 Grade 1, 0402; Manufacturer: Kemet; Polarized: N; CompType: Capacitor; Value: 0.1uF; U/M: EA; Cap_F: 0.0000001; Tolerance_%: 10; VDC_V: 16; Value2: 16V; TaMin_C: -55; TaMax_C: 125; Cap_Case: 0402; SizeArea_mm2: 0.5; SizeAreaWB_mm2: 3; SizeX_mm: 1; SizeZ_mm: 0.6; AEC Category: Q200; AEC Qualified: Y; Green_Lifecycle: Active; Green_REACh: Passed
signal-integrity model Cap
simulation model Cap
footprint 0402
footprint 0402M
footprint 0402L
footprint 0402S
pins: 1, 2

## C0402C112J5GAC7867
designator C?  ValueDisplayed: 1100pF  (hidden comment: C0402C112J5GAC7867)
CAP, CERM, 1100 pF, 50 V,+/- 5%, C0G/NP0, 0402; Manufacturer: Kemet; Polarized: N; CompType: Capacitor; Value: 1100pF; U/M: EA; Cap_F: 0.0000000011; Tolerance_%: 5; VDC_V: 50; Value2: 50V; TaMin_C: -55; TaMax_C: 125; Cap_Case: 0402; SizeArea_mm2: 0.5; SizeAreaWB_mm2: 3; SizeX_mm: 1; SizeZ_mm: 0.6; AEC Category: Q200; Green_Lifecycle: Not Set; Green_REACh: Incomplete
signal-integrity model Cap
simulation model Cap
footprint 0402
footprint 0402M
footprint 0402L
footprint 0402S
pins: 1, 2

## C0402C120J3GACAUTO
designator C?  ValueDisplayed: 12pF  (hidden comment: C0402C120J3GACAUTO)
CAP, CERM, 12 pF, 25 V,+/- 5%, C0G/NP0, AEC-Q200 Grade 1, 0402; Manufacturer: Kemet; Polarized: N; CompType: Capacitor; Value: 12pF; U/M: EA; Cap_F: 0.000000000012; Tolerance_%: 5; VDC_V: 25; Value2: 25V; TaMin_C: -55; TaMax_C: 125; Cap_Case: 0402; SizeArea_mm2: 0.5; SizeAreaWB_mm2: 3; SizeX_mm: 1; SizeZ_mm: 0.6; AEC Category: Q200; AEC Qualified: Y; Green_Lifecycle: Not Set; Green_REACh: Incomplete
signal-integrity model Cap
simulation model Cap
footprint 0402
footprint 0402M
footprint 0402L
footprint 0402S
pins: 1, 2

## C0402C122J5GACTU
designator C?  ValueDisplayed: 1200pF  (hidden comment: C0402C122J5GACTU)
CAP, CERM, 1200 pF, 50 V,+/- 5%, C0G/NP0, 0402; Manufacturer: Kemet; Polarized: N; CompType: Capacitor; Value: 1200pF; U/M: EA; Cap_F: 0.0000000012; Tolerance_%: 5; VDC_V: 50; Value2: 50V; TaMin_C: -55; TaMax_C: 125; Cap_Case: 0402; SizeArea_mm2: 0.5; SizeAreaWB_mm2: 3; SizeX_mm: 1; SizeZ_mm: 0.6; AEC Category: Q200; Green_Lifecycle: Not Set; Green_REACh: Incomplete
signal-integrity model Cap
simulation model Cap
footprint 0402
footprint 0402M
footprint 0402L
footprint 0402S
pins: 1, 2

## C0402C200J5GACTU
designator C?  ValueDisplayed: 20pF  (hidden comment: C0402C200J5GACTU)
CAP, CERM, 20 pF, 50 V,+/- 5%, C0G/NP0, 0402; Manufacturer: Kemet; Polarized: N; CompType: Capacitor; Value: 20pF; U/M: EA; Cap_F: 0.00000000002; Tolerance_%: 5; VDC_V: 50; Value2: 50V; TaMin_C: -55; TaMax_C: 125; Cap_Case: 0402; SizeArea_mm2: 0.5; SizeAreaWB_mm2: 3; SizeX_mm: 1; SizeZ_mm: 0.6; AEC Category: Q200; Green_Lifecycle: Not Set; Green_REACh: Incomplete
signal-integrity model Cap
simulation model Cap
footprint 0402
footprint 0402M
footprint 0402L
footprint 0402S
pins: 1, 2

## C0402C330J5GAC
designator C?  ValueDisplayed: 33pF  (hidden comment: C0402C330J5GAC)
CAP, CERM, 33 pF, 50 V,+/- 5%, C0G/NP0, 0402; Manufacturer: Kemet; Polarized: N; CompType: Capacitor; Value: 33pF; U/M: EA; Cap_F: 0.000000000033; Tolerance_%: 5; VDC_V: 50; Value2: 50V; TaMin_C: -55; TaMax_C: 125; Cap_Case: 0402; SizeArea_mm2: 0.5; SizeAreaWB_mm2: 3; SizeX_mm: 1; SizeZ_mm: 0.6; AEC Category: Q200; Green_Lifecycle: Active; Green_REACh: Passed
signal-integrity model Cap
simulation model Cap
footprint 0402
footprint 0402M
footprint 0402L
footprint 0402S
pins: 1, 2

## C0402C392K4RACTU
designator C?  ValueDisplayed: 3900pF  (hidden comment: C0402C392K4RACTU)
CAP, CERM, 3900 pF, 16 V,+/- 10%, X7R, 0402; Manufacturer: Kemet; Polarized: N; CompType: Capacitor; Value: 3900pF; U/M: EA; Cap_F: 0.0000000039; Tolerance_%: 10; VDC_V: 16; Value2: 16V; TaMin_C: -55; TaMax_C: 125; Cap_Case: 0402; SizeArea_mm2: 0.5; SizeAreaWB_mm2: 3; SizeX_mm: 1; SizeZ_mm: 0.6; AEC Category: Q200
signal-integrity model Cap
simulation model Cap
footprint 0402
footprint 0402M
footprint 0402L
footprint 0402S
pins: 1, 2

## C0402C823K4RACTU
designator C?  ValueDisplayed: 0.082µF  (hidden comment: C0402C823K4RACTU)
CAP, CERM, 0.082 µF, 10 V,+/- 10%, X7R, 0402; Manufacturer: Kemet; Polarized: N; CompType: Capacitor; Value: 0.082uF; U/M: EA; Cap_F: 0.000000082; Tolerance_%: 10; Value2: 10V; TaMin_C: -55; TaMax_C: 125; Cap_Case: 0402; SizeArea_mm2: 0.5; SizeAreaWB_mm2: 3; SizeX_mm: 1; SizeZ_mm: 0.6; AEC Category: Q200
signal-integrity model Cap
simulation model Cap
footprint 0402
footprint 0402M
footprint 0402L
footprint 0402S
pins: 1, 2

## C0402H152J3GAC7867
designator C?  ValueDisplayed: 1500pF  (hidden comment: C0402H152J3GAC7867)
CAP, CERM, 1500 pF, 25 V,+/- 5%, C0G/NP0, 0402; Manufacturer: Kemet; Polarized: N; CompType: Capacitor; Value: 1500pF; U/M: EA; Cap_F: 0.0000000015; Tolerance_%: 5; VDC_V: 25; Value2: 25V; TaMin_C: -55; TaMax_C: 200; Cap_Case: 0402; SizeArea_mm2: 0.5; SizeAreaWB_mm2: 3; SizeX_mm: 1; SizeZ_mm: 0.6; AEC Category: Q200; Green_Lifecycle: Not Set; Green_REACh: Incomplete
signal-integrity model Cap
simulation model Cap
footprint 0402
footprint 0402M
footprint 0402L
footprint 0402S
pins: 1, 2

## C0402X5R0J332K020BC
designator C?  ValueDisplayed: 3300pF  (hidden comment: C0402X5R0J332K020BC)
CAP, CERM, 3300 pF, 6.3 V,+/- 10%, X5R, 01005; Manufacturer: TDK; Polarized: N; CompType: Capacitor; Value: 3300pF; U/M: EA; Cap_F: 0.0000000033; Tolerance_%: 10; VDC_V: 6.3; Value2: 6.3V; TaMin_C: -55; TaMax_C: 85; Cap_Case: 01005; SizeArea_mm2: 0.08; SizeAreaWB_mm2: 1.68; SizeX_mm: 0.4; SizeY_mm: 0.2; AEC Category: Q200; Green_Lifecycle: EOL; Green_REACh: Passed
signal-integrity model Cap
simulation model Cap
footprint 01005
pins: 1, 2

## C430C752FAG5TA7200
designator C?  ValueDisplayed: 7500pF  (hidden comment: C430C752FAG5TA7200)
CAP, CERM, 7500 pF, 250 V,+/- 1%, C0G, D3.81xL6.1mm; Manufacturer: Kemet; Polarized: N; CompType: Capacitor; Value: 7500pF; U/M: EA; Cap_F: 0.0000000075; Tolerance_%: 1; VDC_V: 250; Value2: 250V; TaMin_C: -55; TaMax_C: 125; Cap_Case: 3.81x6.1mm; SizeArea_mm2: 40.386; SizeAreaWB_mm2: 73.206; SizeX_mm: 10.6; SizeY_mm: 3.81; AEC Category: Q200
signal-integrity model Cap
simulation model Cap
footprint C430_381x610
pins: 1, 2

## C0603C0G1E101J030BA
designator C?  ValueDisplayed: 100pF  (hidden comment: C0603C0G1E101J030BA)
CAP, CERM, 100 pF, 25 V,+/- 5%, C0G/NP0, 0201; Manufacturer: TDK; Polarized: N; CompType: Capacitor; Value: 100pF; U/M: EA; Cap_F: 0.0000000001; Tolerance_%: 5; VDC_V: 25; Value2: 25V; TaMin_C: -55; TaMax_C: 125; Cap_Case: 0201; SizeArea_mm2: 0.18; SizeAreaWB_mm2: 2.08; SizeX_mm: 0.6; SizeY_mm: 0.3; SizeZ_mm: 0.33; AEC Category: Q200; Green_Lifecycle: Active; Green_REACh: Passed
signal-integrity model Cap
simulation model Cap
footprint 0201_033
footprint 0201_033M
footprint 0201_033L
pins: 1, 2

## C0603C0G1E120J030BA
designator C?  ValueDisplayed: 12pF  (hidden comment: C0603C0G1E120J030BA)
CAP, CERM, 12 pF, 25 V,+/- 5%, C0G/NP0, 0201; Manufacturer: TDK; Polarized: N; CompType: Capacitor; Value: 12pF; U/M: EA; Cap_F: 0.000000000012; Tolerance_%: 5; ESR_ohm: 0; Value1: 0 ohm; VDC_V: 25; Value2: 25V; TaMin_C: -55; TaMax_C: 125; Cap_Case: 0201; SizeArea_mm2: 0.18; SizeAreaWB_mm2: 2.08; SizeX_mm: 0.6; SizeY_mm: 0.3; SizeZ_mm: 0.33; AEC Category: Q200; Green_Lifecycle: Not Set; Green_REACh: Incomplete
signal-integrity model Cap
simulation model Cap
footprint 0201_033
footprint 0201_033M
footprint 0201_033L
pins: 1, 2

## C0603C100F5GAC7867
designator C?  ValueDisplayed: 10pF  (hidden comment: C0603C100F5GAC7867)
CAP, CERM, 10 pF, 50 V,+/- 1%, C0G/NP0, 0603; Manufacturer: Kemet; Polarized: N; CompType: Capacitor; Value: 10pF; U/M: EA; Cap_F: 0.00000000001; Tolerance_%: 1; VDC_V: 50; Value2: 50V; TaMin_C: -55; TaMax_C: 125; Cap_Case: 0603; SizeArea_mm2: 1.28; SizeAreaWB_mm2: 4.68; SizeX_mm: 1.6; SizeY_mm: 0.8; AEC Category: Q200; Green_Lifecycle: Active; Green_REACh: Passed
signal-integrity model Cap
simulation model Cap
footprint 0603
footprint 0603M
footprint 0603L
footprint 0603_HV
footprint 0603S
pins: 1, 2

## C0603C100J5GACTU
designator C?  ValueDisplayed: 10pF  (hidden comment: C0603C100J5GACTU)
CAP, CERM, 10 pF, 50 V,+/- 5%, C0G/NP0, 0603; Manufacturer: Kemet; Polarized: N; CompType: Capacitor; Value: 10pF; U/M: EA; Cap_F: 0.00000000001; Tolerance_%: 5; VDC_V: 50; Value2: 50V; TaMin_C: -55; TaMax_C: 125; Cap_Case: 0603; SizeArea_mm2: 1.28; SizeAreaWB_mm2: 4.68; SizeX_mm: 1.6; SizeY_mm: 0.8; SizeZ_mm: 1; AEC Category: Q200; Green_Lifecycle: Active; Green_REACh: Passed
signal-integrity model Cap
simulation model Cap
footprint 0603
footprint 0603M
footprint 0603L
footprint 0603_HV
footprint 0603S
pins: 1, 2

## C0603C101J5GAC
designator C?  ValueDisplayed: 100pF  (hidden comment: C0603C101J5GAC)
CAP, CERM, 100 pF, 50 V,+/- 5%, C0G/NP0, 0603; Manufacturer: Kemet; Polarized: N; CompType: Capacitor; Value: 100pF; U/M: EA; Cap_F: 0.0000000001; Tolerance_%: 5; VDC_V: 50; Value2: 50V; TaMin_C: -55; TaMax_C: 125; Cap_Case: 0603; SizeArea_mm2: 1.28; SizeAreaWB_mm2: 4.68; SizeX_mm: 1.6; SizeY_mm: 0.8; SizeZ_mm: 1; AEC Category: Q200; Green_Lifecycle: Active; Green_REACh: Passed
signal-integrity model Cap
simulation model Cap
footprint 0603
footprint 0603M
footprint 0603L
footprint 0603_HV
footprint 0603S
pins: 1, 2

## C0603C101J5GACTU
designator C?  ValueDisplayed: 100pF  (hidden comment: C0603C101J5GACTU)
CAP, CERM, 100 pF, 50 V,+/- 5%, C0G/NP0, 0603; Manufacturer: Kemet; Polarized: N; CompType: Capacitor; Value: 100pF; U/M: EA; Cap_F: 0.0000000001; Tolerance_%: 5; VDC_V: 50; Value2: 50V; TaMin_C: -55; TaMax_C: 125; Cap_Case: 0603; SizeArea_mm2: 1.28; SizeAreaWB_mm2: 4.68; SizeX_mm: 1.6; SizeY_mm: 0.8; SizeZ_mm: 1; AEC Category: Q200; Green_Lifecycle: Active; Green_REACh: Passed
signal-integrity model Cap
simulation model Cap
footprint 0603
footprint 0603M
footprint 0603L
footprint 0603_HV
footprint 0603S
pins: 1, 2

## C0603C102J5GAC
designator C?  ValueDisplayed: 1000pF  (hidden comment: C0603C102J5GAC)
CAP, CERM, 1000 pF, 50 V,+/- 5%, C0G/NP0, 0603; Manufacturer: Kemet; Polarized: N; CompType: Capacitor; Value: 1000pF; U/M: EA; Cap_F: 0.000000001; Tolerance_%: 5; VDC_V: 50; Value2: 50V; TaMin_C: -55; TaMax_C: 125; Cap_Case: 0603; SizeArea_mm2: 1.28; SizeAreaWB_mm2: 4.68; SizeX_mm: 1.6; SizeY_mm: 0.8; SizeZ_mm: 1; AEC Category: Q200; Green_Lifecycle: Active; Green_REACh: Passed
signal-integrity model Cap
simulation model Cap
footprint 0603
footprint 0603M
footprint 0603L
footprint 0603_HV
footprint 0603S
pins: 1, 2

## C0603C102J5GACTU
designator C?  ValueDisplayed: 1000pF  (hidden comment: C0603C102J5GACTU)
CAP, CERM, 1000 pF, 50 V,+/- 5%, C0G/NP0, 0603; Manufacturer: Kemet; Polarized: N; CompType: Capacitor; Value: 1000pF; U/M: EA; Cap_F: 0.000000001; Tolerance_%: 5; VDC_V: 50; Value2: 50V; TaMin_C: -55; TaMax_C: 125; Cap_Case: 0603; SizeArea_mm2: 1.28; SizeAreaWB_mm2: 4.68; SizeX_mm: 1.6; SizeY_mm: 0.8; SizeZ_mm: 1; AEC Category: Q200; Green_Lifecycle: Active; Green_REACh: Passed
signal-integrity model Cap
simulation model Cap
footprint 0603
footprint 0603M
footprint 0603L
footprint 0603_HV
footprint 0603S
pins: 1, 2

## C0603C102J5RACAUTO
designator C?  ValueDisplayed: 1000pF  (hidden comment: C0603C102J5RACAUTO)
CAP, CERM, 1000 pF, 50 V,+/- 5%, X7R, AEC-Q200 Grade 1, 0603; Manufacturer: Kemet; Polarized: N; CompType: Capacitor; Value: 1000pF; U/M: EA; Cap_F: 0.000000001; Tolerance_%: 5; VDC_V: 50; Value2: 50V; TaMin_C: -55; TaMax_C: 125; Cap_Case: 0603; SizeArea_mm2: 1.28; SizeAreaWB_mm2: 4.68; SizeX_mm: 1.6; SizeY_mm: 0.8; SizeZ_mm: 1; AEC Category: Q200; AEC Qualified: Y
signal-integrity model Cap
simulation model Cap
footprint 0603
footprint 0603M
footprint 0603L
footprint 0603_HV
footprint 0603S
pins: 1, 2

## C0603C102J5RACTU
designator C?  ValueDisplayed: 1000pF  (hidden comment: C0603C102J5RACTU)
CAP, CERM, 1000 pF, 50 V,+/- 5%, X7R, 0603; Manufacturer: Kemet; Polarized: N; CompType: Capacitor; Value: 1000pF; U/M: EA; Cap_F: 0.000000001; Tolerance_%: 5; VDC_V: 50; Value2: 50V; TaMin_C: -55; TaMax_C: 125; Cap_Case: 0603; SizeArea_mm2: 1.28; SizeAreaWB_mm2: 4.68; SizeX_mm: 1.6; SizeY_mm: 0.8; SizeZ_mm: 1; AEC Category: Q200; Green_Lifecycle: Active; Green_REACh: Passed
signal-integrity model Cap
simulation model Cap
footprint 0603
footprint 0603M
footprint 0603L
footprint 0603_HV
footprint 0603S
pins: 1, 2

## C0603C102K3GACTU
designator C?  ValueDisplayed: 1000pF  (hidden comment: C0603C102K3GACTU)
CAP, CERM, 1000 pF, 25 V,+/- 10%, C0G/NP0, 0603; Manufacturer: Kemet; Polarized: N; CompType: Capacitor; Value: 1000pF; U/M: EA; Cap_F: 0.000000001; Tolerance_%: 10; ESR_ohm: 0; Value1: 0 ohm; VDC_V: 25; Value2: 25V; TaMin_C: -55; TaMax_C: 125; Cap_Case: 0603; SizeArea_mm2: 1.28; SizeAreaWB_mm2: 4.68; SizeX_mm: 1.6; SizeY_mm: 0.8; SizeZ_mm: 1; AEC Category: Q200; Green_Lifecycle: Not Set; Green_REACh: Incomplete
signal-integrity model Cap
simulation model Cap
footprint 0603
footprint 0603M
footprint 0603L
footprint 0603_HV
footprint 0603S
pins: 1, 2

## C0603C102K5RACTU
designator C?  ValueDisplayed: 1000pF  (hidden comment: C0603C102K5RACTU)
CAP, CERM, 1000 pF, 50 V,+/- 10%, X7R, 0603; Manufacturer: Kemet; Polarized: N; CompType: Capacitor; Value: 1000pF; U/M: EA; Cap_F: 0.000000001; Tolerance_%: 10; VDC_V: 50; Value2: 50V; TaMin_C: -55; TaMax_C: 125; Cap_Case: 0603; SizeArea_mm2: 1.28; SizeAreaWB_mm2: 4.68; SizeX_mm: 1.6; SizeY_mm: 0.8; SizeZ_mm: 1; AEC Category: Q200; Green_Lifecycle: Active; Green_REACh: Passed
signal-integrity model Cap
simulation model Cap
footprint 0603
footprint 0603M
footprint 0603L
footprint 0603_HV
footprint 0603S
pins: 1, 2

## C0603C103J1RACTU
designator C?  ValueDisplayed: 0.01µF  (hidden comment: C0603C103J1RACTU)
CAP, CERM, 0.01 µF, 100 V,+/- 5%, X7R, 0603; Manufacturer: Kemet; Polarized: N; CompType: Capacitor; Value: 0.01uF; U/M: EA; Cap_F: 0.00000001; Tolerance_%: 5; VDC_V: 100; Value2: 100V; TaMin_C: -55; TaMax_C: 125; Cap_Case: 0603; SizeArea_mm2: 1.28; SizeAreaWB_mm2: 4.68; SizeX_mm: 1.6; SizeY_mm: 0.8; SizeZ_mm: 1; AEC Category: Q200; Green_Lifecycle: Active; Green_REACh: Passed
signal-integrity model Cap
simulation model Cap
footprint 0603
footprint 0603M
footprint 0603L
footprint 0603_HV
footprint 0603S
pins: 1, 2

## C0603C103J3GECAUTO
designator C?  ValueDisplayed: 0.01µF  (hidden comment: C0603C103J3GECAUTO)
CAP, CERM, 0.01 µF, 25 V,+/- 5%, C0G/NP0, AEC-Q200 Grade 1, 0603; Manufacturer: Kemet; Polarized: N; CompType: Capacitor; Value: 0.01uF; U/M: EA; Cap_F: 0.00000001; Tolerance_%: 5; VDC_V: 25; Value2: 25V; TaMin_C: -55; TaMax_C: 125; Cap_Case: 0603; SizeArea_mm2: 1.28; SizeAreaWB_mm2: 4.68; SizeX_mm: 1.6; SizeY_mm: 0.8; SizeZ_mm: 1; AEC Category: Q200; AEC Qualified: Y
signal-integrity model Cap
simulation model Cap
footprint 0603
footprint 0603M
footprint 0603L
footprint 0603_HV
footprint 0603S
pins: 1, 2

## C0603C103J5RACTU
designator C?  ValueDisplayed: 0.01µF  (hidden comment: C0603C103J5RACTU)
CAP, CERM, 0.01 µF, 50 V,+/- 5%, X7R, 0603; Manufacturer: Kemet; Polarized: N; CompType: Capacitor; Value: 0.01uF; U/M: EA; Cap_F: 0.00000001; Tolerance_%: 5; VDC_V: 50; Value2: 50V; TaMin_C: -55; TaMax_C: 125; Cap_Case: 0603; SizeArea_mm2: 1.28; SizeAreaWB_mm2: 4.68; SizeX_mm: 1.6; SizeY_mm: 0.8; SizeZ_mm: 1; AEC Category: Q200; Green_Lifecycle: Active; Green_REACh: Passed
signal-integrity model Cap
simulation model Cap
footprint 0603
footprint 0603M
footprint 0603L
footprint 0603_HV
footprint 0603S
pins: 1, 2

## C0603C103K1RACTU
designator C?  ValueDisplayed: 0.01µF  (hidden comment: C0603C103K1RACTU)
CAP, CERM, 0.01 µF, 100 V,+/- 10%, X7R, 0603; Manufacturer: Kemet; Polarized: N; CompType: Capacitor; Value: 0.01uF; U/M: EA; Cap_F: 0.00000001; Tolerance_%: 10; VDC_V: 100; Value2: 100V; TaMin_C: -55; TaMax_C: 125; Cap_Case: 0603; SizeArea_mm2: 1.28; SizeAreaWB_mm2: 4.68; SizeX_mm: 1.6; SizeY_mm: 0.8; SizeZ_mm: 1; AEC Category: Q200; Green_Lifecycle: Active; Green_REACh: Passed
signal-integrity model Cap
simulation model Cap
footprint 0603
footprint 0603M
footprint 0603L
footprint 0603_HV
footprint 0603S
pins: 1, 2

## C0603C103K2RACTU
designator C?  ValueDisplayed: 0.01µF  (hidden comment: C0603C103K2RACTU)
CAP, CERM, 0.01 µF, 200 V,+/- 10%, X7R, 0603; Manufacturer: Kemet; Polarized: N; CompType: Capacitor; Value: 0.01uF; U/M: EA; Cap_F: 0.00000001; Tolerance_%: 10; VDC_V: 200; Value2: 200V; TaMin_C: -55; TaMax_C: 125; Cap_Case: 0603; SizeArea_mm2: 1.28; SizeAreaWB_mm2: 4.68; SizeX_mm: 1.6; SizeY_mm: 0.8; SizeZ_mm: 1; AEC Category: Q200; Green_Lifecycle: Not Set; Green_REACh: Incomplete
signal-integrity model Cap
simulation model Cap
footprint 0603
footprint 0603M
footprint 0603L
footprint 0603_HV
footprint 0603S
pins: 1, 2

## C0603C103K4RACTU
designator C?  ValueDisplayed: 0.01µF  (hidden comment: C0603C103K4RACTU)
CAP, CERM, 0.01 µF, 16 V,+/- 10%, X7R, 0603; Manufacturer: Kemet; Polarized: N; CompType: Capacitor; Value: 0.01uF; U/M: EA; Cap_F: 0.00000001; Tolerance_%: 10; VDC_V: 16; Value2: 16V; TaMin_C: -55; TaMax_C: 125; Cap_Case: 0603; SizeArea_mm2: 1.28; SizeAreaWB_mm2: 4.68; SizeX_mm: 1.6; SizeY_mm: 0.8; SizeZ_mm: 1; AEC Category: Q200; Green_Lifecycle: Active; Green_REACh: Passed
signal-integrity model Cap
simulation model Cap
footprint 0603
footprint 0603M
footprint 0603L
footprint 0603_HV
footprint 0603S
pins: 1, 2

## C0603C103K5RACTU
designator C?  ValueDisplayed: 0.01µF  (hidden comment: C0603C103K5RACTU)
CAP, CERM, 0.01 µF, 50 V,+/- 10%, X7R, 0603; Manufacturer: Kemet; Polarized: N; CompType: Capacitor; Value: 0.01uF; U/M: EA; Cap_F: 0.00000001; Tolerance_%: 10; VDC_V: 50; Value2: 50V; TaMin_C: -55; TaMax_C: 125; Cap_Case: 0603; SizeArea_mm2: 1.28; SizeAreaWB_mm2: 4.68; SizeX_mm: 1.6; SizeY_mm: 0.8; SizeZ_mm: 1; AEC Category: Q200; Green_Lifecycle: Active; Green_REACh: Passed
signal-integrity model Cap
simulation model Cap
footprint 0603
footprint 0603M
footprint 0603L
footprint 0603_HV
footprint 0603S
pins: 1, 2

## C0603C104J3RAC
designator C?  ValueDisplayed: 0.1µF  (hidden comment: C0603C104J3RAC)
CAP, CERM, 0.1 µF, 25 V,+/- 5%, X7R, 0603; Manufacturer: Kemet; Polarized: N; CompType: Capacitor; Value: 0.1uF; U/M: EA; Cap_F: 0.0000001; Tolerance_%: 5; VDC_V: 25; Value2: 25V; TaMin_C: -55; TaMax_C: 125; Cap_Case: 0603; SizeArea_mm2: 1.28; SizeAreaWB_mm2: 4.68; SizeX_mm: 1.6; SizeY_mm: 0.8; SizeZ_mm: 1; AEC Category: Q200; Green_Lifecycle: Active; Green_REACh: Passed
signal-integrity model Cap
simulation model Cap
footprint 0603
footprint 0603M
footprint 0603L
footprint 0603_HV
footprint 0603S
pins: 1, 2

## C0603C104J3RACTU
designator C?  ValueDisplayed: 0.1µF  (hidden comment: C0603C104J3RACTU)
CAP, CERM, 0.1 µF, 25 V,+/- 5%, X7R, 0603; Manufacturer: Kemet; Polarized: N; CompType: Capacitor; Value: 0.1uF; U/M: EA; Cap_F: 0.0000001; Tolerance_%: 5; VDC_V: 25; Value2: 25V; TaMin_C: -55; TaMax_C: 125; Cap_Case: 0603; SizeArea_mm2: 1.28; SizeAreaWB_mm2: 4.68; SizeX_mm: 1.6; SizeY_mm: 0.8; SizeZ_mm: 1; AEC Category: Q200; Green_Lifecycle: Active; Green_REACh: Passed
signal-integrity model Cap
simulation model Cap
footprint 0603
footprint 0603M
footprint 0603L
footprint 0603_HV
footprint 0603S
pins: 1, 2

## C0603C104J4RACTU
designator C?  ValueDisplayed: 0.1µF  (hidden comment: C0603C104J4RACTU)
CAP, CERM, 0.1 µF, 16 V,+/- 5%, X7R, 0603; Manufacturer: Kemet; Polarized: N; CompType: Capacitor; Value: 0.1uF; U/M: EA; Cap_F: 0.0000001; Tolerance_%: 5; VDC_V: 16; Value2: 16V; TaMin_C: -55; TaMax_C: 125; Cap_Case: 0603; SizeArea_mm2: 1.28; SizeAreaWB_mm2: 4.68; SizeX_mm: 1.6; SizeY_mm: 0.8; SizeZ_mm: 1; AEC Category: Q200; Green_Lifecycle: Active; Green_REACh: Passed
signal-integrity model Cap
simulation model Cap
footprint 0603
footprint 0603M
footprint 0603L
footprint 0603_HV
footprint 0603S
pins: 1, 2

## C0603C104J5RACTU
designator C?  ValueDisplayed: 0.1µF  (hidden comment: C0603C104J5RACTU)
CAP, CERM, 0.1 µF, 50 V,+/- 5%, X7R, 0603; Manufacturer: Kemet; Polarized: N; CompType: Capacitor; Value: 0.1uF; U/M: EA; Cap_F: 0.0000001; Tolerance_%: 5; VDC_V: 50; Value2: 50V; TaMin_C: -55; TaMax_C: 125; Cap_Case: 0603; SizeArea_mm2: 1.28; SizeAreaWB_mm2: 4.68; SizeX_mm: 1.6; SizeY_mm: 0.8; SizeZ_mm: 1; AEC Category: Q200; Green_Lifecycle: Not Set; Green_REACh: Incomplete
signal-integrity model Cap
simulation model Cap
footprint 0603
footprint 0603M
footprint 0603L
footprint 0603_HV
footprint 0603S
pins: 1, 2

## C0603C104K3RACTU
designator C?  ValueDisplayed: 0.1µF  (hidden comment: C0603C104K3RACTU)
CAP, CERM, 0.1 µF, 25 V,+/- 10%, X7R, 0603; Manufacturer: Kemet; Polarized: N; CompType: Capacitor; Value: 0.1uF; U/M: EA; Cap_F: 0.0000001; Tolerance_%: 10; VDC_V: 25; Value2: 25V; TaMin_C: -55; TaMax_C: 125; Cap_Case: 0603; SizeArea_mm2: 1.28; SizeAreaWB_mm2: 4.68; SizeX_mm: 1.6; SizeY_mm: 0.8; SizeZ_mm: 1; AEC Category: Q200; Green_Lifecycle: Active; Green_REACh: Passed
signal-integrity model Cap
simulation model Cap
footprint 0603
footprint 0603M
footprint 0603L
footprint 0603_HV
footprint 0603S
pins: 1, 2

## C0603C104K4RACTU
designator C?  ValueDisplayed: 0.1µF  (hidden comment: C0603C104K4RACTU)
CAP, CERM, 0.1 µF, 16 V,+/- 10%, X7R, 0603; Manufacturer: Kemet; Polarized: N; CompType: Capacitor; Value: 0.1uF; U/M: EA; Cap_F: 0.0000001; Tolerance_%: 10; VDC_V: 16; Value2: 16V; TaMin_C: -55; TaMax_C: 125; Cap_Case: 0603; SizeArea_mm2: 1.28; SizeAreaWB_mm2: 4.68; SizeX_mm: 1.6; SizeY_mm: 0.8; SizeZ_mm: 1; AEC Category: Q200; Green_Lifecycle: Active; Green_REACh: Passed
signal-integrity model Cap
simulation model Cap
footprint 0603
footprint 0603M
footprint 0603L
footprint 0603_HV
footprint 0603S
pins: 1, 2

## C0603C104K5RACTU
designator C?  ValueDisplayed: 0.1µF  (hidden comment: C0603C104K5RACTU)
CAP, CERM, 0.1 µF, 50 V,+/- 10%, X7R, 0603; Manufacturer: Kemet; Polarized: N; CompType: Capacitor; Value: 0.1uF; U/M: EA; Cap_F: 0.0000001; Tolerance_%: 10; VDC_V: 50; Value2: 50V; TaMin_C: -55; TaMax_C: 125; Cap_Case: 0603; SizeArea_mm2: 1.28; SizeAreaWB_mm2: 4.68; SizeX_mm: 1.6; SizeY_mm: 0.8; SizeZ_mm: 1; AEC Category: Q200; Green_Lifecycle: Active; Green_REACh: Passed
signal-integrity model Cap
simulation model Cap
footprint 0603
footprint 0603M
footprint 0603L
footprint 0603_HV
footprint 0603S
pins: 1, 2

## C0603C104K8RACTU
designator C?  ValueDisplayed: 0.1µF  (hidden comment: C0603C104K8RACTU)
CAP, CERM, 0.1 µF, 10 V,+/- 10%, X7R, 0603; Manufacturer: Kemet; Polarized: N; CompType: Capacitor; Value: 0.1uF; U/M: EA; Cap_F: 0.0000001; Tolerance_%: 10; Value2: 10V; TaMin_C: -55; TaMax_C: 125; Cap_Case: 0603; SizeArea_mm2: 1.28; SizeAreaWB_mm2: 4.68; SizeX_mm: 1.6; SizeY_mm: 0.8; SizeZ_mm: 1; AEC Category: Q200; Green_Lifecycle: Active; Green_REACh: Passed
signal-integrity model Cap
simulation model Cap
footprint 0603
footprint 0603M
footprint 0603L
footprint 0603_HV
footprint 0603S
pins: 1, 2

## C0603C104M3VACTU
designator C?  ValueDisplayed: 0.1µF  (hidden comment: C0603C104M3VACTU)
CAP, CERM, 0.1 µF, 25 V,+/- 20%, Y5V, 0603; Manufacturer: Kemet; Polarized: N; CompType: Capacitor; Value: 0.1uF; U/M: EA; Cap_F: 0.0000001; Tolerance_%: 20; VDC_V: 25; Value2: 25V; TaMin_C: -30; TaMax_C: 85; Cap_Case: 0603; SizeArea_mm2: 1.28; SizeAreaWB_mm2: 4.68; SizeX_mm: 1.6; SizeY_mm: 0.8; SizeZ_mm: 1; AEC Category: Q200; Green_Lifecycle: Not Set; Green_REACh: Incomplete
signal-integrity model Cap
simulation model Cap
footprint 0603
footprint 0603M
footprint 0603L
footprint 0603_HV
footprint 0603S
pins: 1, 2

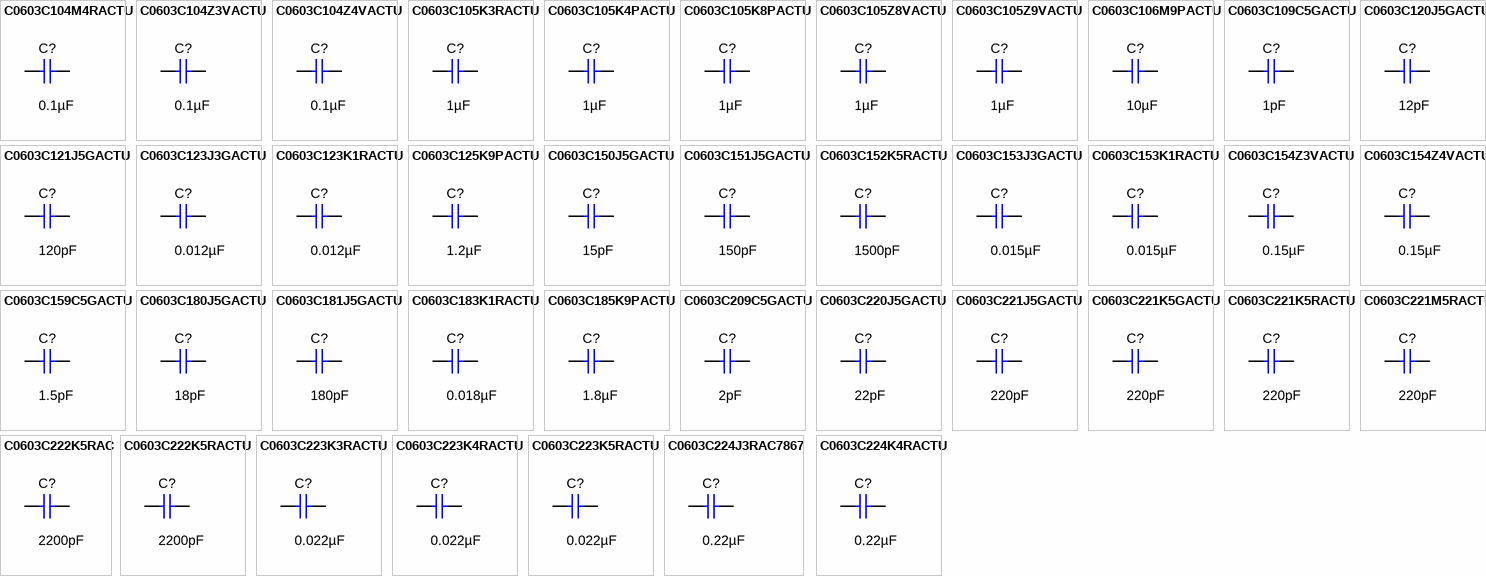
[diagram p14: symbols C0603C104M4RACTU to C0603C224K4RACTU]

## C0603C104M4RACTU
designator C?  ValueDisplayed: 0.1µF  (hidden comment: C0603C104M4RACTU)
CAP, CERM, 0.1 µF, 16 V,+/- 20%, X7R, 0603; Manufacturer: Kemet; Polarized: N; CompType: Capacitor; Value: 0.1uF; U/M: EA; Cap_F: 0.0000001; Tolerance_%: 20; VDC_V: 16; Value2: 16V; TaMin_C: -55; TaMax_C: 125; Cap_Case: 0603; SizeArea_mm2: 1.28; SizeAreaWB_mm2: 4.68; SizeX_mm: 1.6; SizeY_mm: 0.8; SizeZ_mm: 1; AEC Category: Q200; Green_Lifecycle: Active; Green_REACh: Passed
signal-integrity model Cap
simulation model Cap
footprint 0603
footprint 0603M
footprint 0603L
footprint 0603_HV
footprint 0603S
pins: 1, 2

## C0603C104Z3VACTU
designator C?  ValueDisplayed: 0.1µF  (hidden comment: C0603C104Z3VACTU)
CAP, CERM, 0.1 µF, 25 V,+80/-20%, Y5V, 0603; Manufacturer: Kemet; Polarized: N; CompType: Capacitor; Value: 0.1uF; U/M: EA; Cap_F: 0.0000001; Tolerance_%: 80; VDC_V: 25; Value2: 25V; TaMin_C: -30; TaMax_C: 85; Cap_Case: 0603; SizeArea_mm2: 1.28; SizeAreaWB_mm2: 4.68; SizeX_mm: 1.6; SizeY_mm: 0.8; SizeZ_mm: 1; AEC Category: Q200; Green_Lifecycle: Not Set; Green_REACh: Incomplete
signal-integrity model Cap
simulation model Cap
footprint 0603
footprint 0603M
footprint 0603L
footprint 0603_HV
footprint 0603S
pins: 1, 2

## C0603C104Z4VACTU
designator C?  ValueDisplayed: 0.1µF  (hidden comment: C0603C104Z4VACTU)
CAP, CERM, 0.1 µF, 16 V,+80/-20%, Y5V, 0603; Manufacturer: Kemet; Polarized: N; CompType: Capacitor; Value: 0.1uF; U/M: EA; Cap_F: 0.0000001; Tolerance_%: 80; VDC_V: 16; Value2: 16V; TaMin_C: -30; TaMax_C: 85; Cap_Case: 0603; SizeArea_mm2: 1.28; SizeAreaWB_mm2: 4.68; SizeX_mm: 1.6; SizeY_mm: 0.8; SizeZ_mm: 1; AEC Category: Q200; Green_Lifecycle: Not Set; Green_REACh: Incomplete
signal-integrity model Cap
simulation model Cap
footprint 0603
footprint 0603M
footprint 0603L
footprint 0603_HV
footprint 0603S
pins: 1, 2

## C0603C105K3RACTU
designator C?  ValueDisplayed: 1µF  (hidden comment: C0603C105K3RACTU)
CAP, CERM, 1 µF, 25 V,+/- 10%, X7R, 0603; Manufacturer: Kemet; Polarized: N; CompType: Capacitor; Value: 1uF; U/M: EA; Cap_F: 0.000001; Tolerance_%: 10; VDC_V: 25; Value2: 25V; TaMin_C: -55; TaMax_C: 125; Cap_Case: 0603; SizeArea_mm2: 1.28; SizeAreaWB_mm2: 4.68; SizeX_mm: 1.6; SizeY_mm: 0.8; SizeZ_mm: 1; AEC Category: Q200; Green_Lifecycle: Active; Green_REACh: Passed
signal-integrity model Cap
simulation model Cap
footprint 0603
footprint 0603M
footprint 0603L
footprint 0603_HV
footprint 0603S
pins: 1, 2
